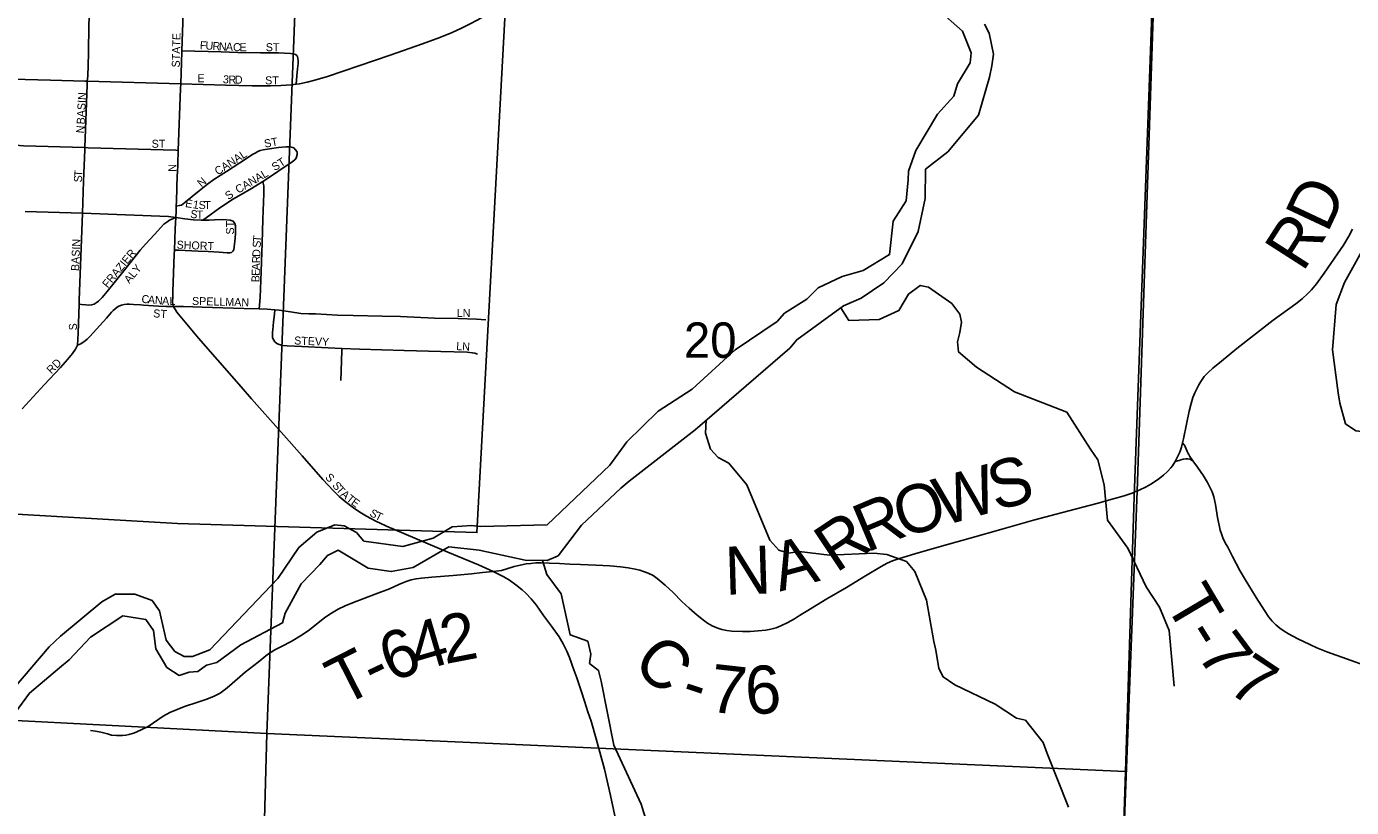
# Model space of a CAD drawing. Extents: x 0 to 34, y 0 to 22.
# Drawn here: x 4.796 to 6.364, y 17.372 to 18.295 of the extents above; entities that cross this region are included whole.
import ezdxf

# ---------------------------------------------------------------- set-up
doc = ezdxf.new("R2010")
doc.units = 0
for name, color, linetype in [('GM_X_City_Street', 7, 'Continuous'), ('GM_X_City_Street_Text', 7, 'Continuous'), ('GM_X_Corporation', 7, 'Continuous'), ('GM_X_County_Road', 7, 'Continuous'), ('GM_X_County_Road_Text', 7, 'Continuous'), ('GM_X_Minor_River', 7, 'Continuous'), ('GM_X_Section', 7, 'Continuous'), ('GM_X_Section_Text', 7, 'Continuous'), ('GM_X_Township', 7, 'Continuous'), ('GM_X_Township_Road', 7, 'Continuous'), ('GM_X_Township_Road_Text', 7, 'Continuous')]:
    doc.layers.add(name, color=color, linetype=linetype)

msp = doc.modelspace()

# ---------------------------------------------------------------- linework, layer by layer
at = {"layer": 'GM_X_City_Street'}
for points in [[(4.8682, 18.2305), (4.8687, 18.2363), (4.8694, 18.2629), (4.8698, 18.2978), (4.8705, 18.3045), (4.8711, 18.3097)], [(4.98, 18.2664), (4.981, 18.2999), (4.9811, 18.3058)], [(5.1151, 18.2271), (5.1191, 18.2276), (5.1284, 18.2294), (5.1375, 18.2316), (5.1525, 18.2361), (5.2263, 18.2613), (5.2647, 18.2746), (5.2852, 18.2822), (5.2997, 18.288), (5.311, 18.2933), (5.3194, 18.2975), (5.3303, 18.3032), (5.3347, 18.3059)], [(4.9787, 18.2274), (4.9799, 18.2657), (4.98, 18.2664)], [(4.98, 18.2664), (5.0264, 18.2653), (5.0464, 18.2644), (5.0731, 18.2641), (5.0945, 18.2639), (5.1084, 18.2634), (5.1117, 18.2629), (5.1144, 18.2622), (5.1159, 18.261)], [(5.1151, 18.2271), (5.116, 18.2367), (5.1169, 18.2452), (5.1173, 18.2484), (5.1175, 18.2516), (5.1175, 18.2547), (5.1173, 18.2578), (5.117, 18.2593), (5.1159, 18.261)], [(4.7065, 18.2354), (4.7098, 18.2351), (4.7498, 18.2337), (4.8247, 18.2318), (4.8651, 18.2306), (4.8682, 18.2305)], [(4.8652, 18.152), (4.8679, 18.2262), (4.8682, 18.2305)], [(4.8682, 18.2305), (4.9787, 18.2274)], [(4.9757, 18.1487), (4.9785, 18.2219), (4.9787, 18.2274)], [(4.9787, 18.2274), (5.0318, 18.2259), (5.063, 18.225), (5.0848, 18.2249), (5.0973, 18.2253), (5.1098, 18.2263), (5.1151, 18.2271)], [(4.7769, 18.1564), (4.7804, 18.1553), (4.7834, 18.1548), (4.7926, 18.1542), (4.8652, 18.152)], [(4.8624, 18.0744), (4.8638, 18.1124), (4.8651, 18.1493), (4.8652, 18.152)], [(4.8652, 18.152), (4.8692, 18.1519), (4.9727, 18.1488), (4.9757, 18.1487)], [(4.9734, 18.0828), (4.977, 18.0834), (4.9794, 18.0841), (4.9811, 18.0852), (4.984, 18.0874), (5.0003, 18.1007), (5.0103, 18.1086), (5.0177, 18.1141), (5.033, 18.1237), (5.0563, 18.1391), (5.0641, 18.1441), (5.0668, 18.1456), (5.07, 18.1474), (5.0728, 18.1484), (5.0761, 18.1493), (5.0837, 18.1505), (5.0943, 18.1521), (5.1033, 18.1529), (5.1064, 18.1531), (5.1094, 18.1527), (5.1112, 18.1522), (5.1123, 18.1516), (5.1145, 18.1495)], [(4.9747, 18.1218), (4.9751, 18.133), (4.9757, 18.1487)], [(5.0758, 18.1119), (5.0779, 18.1131), (5.1104, 18.1352), (5.1135, 18.1377), (5.1154, 18.1397), (5.1165, 18.1439), (5.1165, 18.1454), (5.1163, 18.1465), (5.1161, 18.1473), (5.1145, 18.1495)], [(4.9734, 18.0828), (4.9735, 18.0887), (4.9746, 18.1199), (4.9747, 18.1218)], [(5.0049, 18.0663), (5.0089, 18.0691), (5.0251, 18.0807), (5.0412, 18.0914), (5.0502, 18.0965), (5.0623, 18.1038), (5.0758, 18.1119)], [(5.0715, 17.9613), (5.0718, 17.9655), (5.0725, 17.9748), (5.0737, 18.0056), (5.0752, 18.0394), (5.0759, 18.0669), (5.077, 18.0977), (5.077, 18.1036), (5.0768, 18.1067), (5.0762, 18.1098), (5.0758, 18.1119)], [(4.7946, 18.0763), (4.8624, 18.0744)], [(4.8584, 17.9667), (4.8586, 17.9714), (4.8624, 18.0744)], [(4.8624, 18.0744), (4.9642, 18.0704), (4.9728, 18.0692)], [(4.9728, 18.0692), (4.9732, 18.0768), (4.9734, 18.0828)], [(4.8584, 17.9667), (4.8612, 17.9665), (4.8666, 17.966), (4.8701, 17.9656), (4.8732, 17.9659), (4.8761, 17.9668), (4.8788, 17.9684), (4.8813, 17.9703), (4.8857, 17.9747), (4.8917, 17.982), (4.9115, 18.0062), (4.9308, 18.0308), (4.9369, 18.038), (4.9476, 18.0493), (4.9588, 18.0613), (4.9621, 18.0638), (4.9655, 18.066), (4.9728, 18.0692)], [(4.9713, 18.0308), (4.9723, 18.056), (4.9728, 18.0692)], [(4.9713, 18.0308), (4.9763, 18.0306), (4.9993, 18.0297), (5.0113, 18.0291), (5.0243, 18.0284), (5.0337, 18.0276), (5.0369, 18.0276), (5.0386, 18.028), (5.0404, 18.0294), (5.0414, 18.0312), (5.0419, 18.0345), (5.0426, 18.0409), (5.0434, 18.0501), (5.0436, 18.0564), (5.0433, 18.0596), (5.0426, 18.0623)], [(4.9728, 18.0692), (4.9834, 18.0678), (4.9937, 18.0667), (5.0029, 18.0663), (5.0049, 18.0663)], [(5.0049, 18.0663), (5.0122, 18.0663), (5.0185, 18.0666), (5.0279, 18.0668), (5.033, 18.0666), (5.0373, 18.0662), (5.0395, 18.0656), (5.0408, 18.0649), (5.0417, 18.0639), (5.0426, 18.0623)], [(4.9702, 17.9641), (4.9698, 17.9647), (4.9693, 17.9666), (4.969, 17.9696), (4.9692, 17.9757), (4.9694, 17.9819), (4.9711, 18.0256), (4.9713, 18.0308)], [(4.8566, 17.9182), (4.8604, 17.92), (4.8655, 17.9234), (4.868, 17.9256), (4.8711, 17.9285), (4.8908, 17.9503), (4.8967, 17.9573), (4.8987, 17.9593), (4.9011, 17.9615), (4.9036, 17.9634), (4.9053, 17.9645), (4.9087, 17.9657), (4.9117, 17.9663), (4.9151, 17.9668), (4.9179, 17.9668), (4.9227, 17.9666), (4.9309, 17.9662), (4.9346, 17.9658), (4.9522, 17.9646), (4.9614, 17.9641), (4.9702, 17.9641)], [(4.8566, 17.9182), (4.8573, 17.9327), (4.8584, 17.9667)], [(4.9702, 17.9641), (4.9759, 17.964), (4.9821, 17.964), (5.0039, 17.9635), (5.0532, 17.9619), (5.0715, 17.9613)], [(5.2287, 17.7015), (5.2265, 17.7025), (5.2096, 17.7104), (5.1986, 17.7161), (5.1906, 17.7209), (5.183, 17.726), (5.1731, 17.7335), (5.1661, 17.7395), (5.1595, 17.746), (5.1469, 17.7596), (5.1222, 17.7875), (5.0974, 17.8153), (5.0625, 17.8548), (5.0503, 17.869), (5.0223, 17.9012), (4.9999, 17.9268), (4.9759, 17.9551), (4.9741, 17.9575), (4.9724, 17.9601), (4.9709, 17.9626), (4.9702, 17.9641)], [(5.0715, 17.9613), (5.081, 17.961), (5.0901, 17.9603)], [(5.0901, 17.9603), (5.0896, 17.9552), (5.0886, 17.946), (5.0875, 17.9367), (5.0872, 17.9336), (5.0871, 17.9302), (5.0874, 17.9276), (5.088, 17.9256), (5.0889, 17.9241), (5.0902, 17.9222), (5.0922, 17.9205), (5.0953, 17.9191), (5.0994, 17.918), (5.1047, 17.9175), (5.1219, 17.9167), (5.1529, 17.9151), (5.1693, 17.9145)], [(5.0901, 17.9603), (5.095, 17.9598), (5.1085, 17.9577), (5.1207, 17.9557), (5.1302, 17.9553), (5.1381, 17.9555), (5.151, 17.9547), (5.1641, 17.9539), (5.1827, 17.9533), (5.2169, 17.9528), (5.2386, 17.9522), (5.2789, 17.9505), (5.3069, 17.9498), (5.3286, 17.9491), (5.3395, 17.9484)], [(4.791, 17.843), (4.8172, 17.8715), (4.8363, 17.892), (4.8447, 17.9013), (4.8506, 17.9084), (4.8544, 17.9137), (4.8566, 17.9182)], [(5.1682, 17.8764), (5.1693, 17.9117), (5.1693, 17.9145)], [(5.1693, 17.9145), (5.1901, 17.9138), (5.2429, 17.9121), (5.2864, 17.911), (5.3174, 17.9101), (5.3235, 17.9095), (5.3266, 17.9089), (5.3296, 17.9079)]]:
    msp.add_lwpolyline(points, dxfattribs=at)
at = {"layer": 'GM_X_Corporation'}
msp.add_lwpolyline([(5.3632, 18.3273), (5.329, 17.6967), (4.9748, 17.7073), (4.5871, 17.7299)], dxfattribs=at)
at = {"layer": 'GM_X_County_Road'}
for points in [[(6.1637, 17.8028), (6.1649, 17.8078), (6.1685, 17.825), (6.1718, 17.8405), (6.1741, 17.8495), (6.1761, 17.8565), (6.1784, 17.8621), (6.1806, 17.8669), (6.1831, 17.8716), (6.1853, 17.8756), (6.1893, 17.8812), (6.1941, 17.8862), (6.1998, 17.8911), (6.2097, 17.8994), (6.2279, 17.9145), (6.2708, 17.9479), (6.2979, 17.9673), (6.3052, 17.973), (6.312, 17.9793), (6.3163, 17.9838), (6.3221, 17.9909), (6.3312, 18.0035), (6.3471, 18.0264), (6.354, 18.0368), (6.3604, 18.0473), (6.3648, 18.0555)], [(6.1552, 17.7809), (6.158, 17.7863), (6.1605, 17.792), (6.1625, 17.7978), (6.1637, 17.8028)], [(6.1083, 17.7452), (6.11, 17.7459), (6.1126, 17.7469), (6.1209, 17.751), (6.1263, 17.754), (6.134, 17.7591), (6.1413, 17.7647), (6.1459, 17.7688), (6.15, 17.7734), (6.1519, 17.7758), (6.1552, 17.7809)], [(5.3483, 17.6507), (5.358, 17.6521), (5.3643, 17.6539), (5.373, 17.6565), (5.3822, 17.6586), (5.3873, 17.6597), (5.3927, 17.6602), (5.3989, 17.6609), (5.4051, 17.661), (5.4144, 17.6607), (5.4267, 17.6601), (5.4391, 17.6595), (5.4515, 17.659), (5.4607, 17.6586), (5.4699, 17.6582), (5.4862, 17.6574), (5.499, 17.6562), (5.5081, 17.655), (5.5162, 17.6536), (5.5217, 17.6522), (5.5262, 17.6508), (5.5316, 17.6489), (5.5375, 17.6458), (5.5423, 17.6425), (5.5472, 17.6386), (5.5516, 17.6347), (5.5613, 17.6258), (5.5715, 17.6153), (5.5801, 17.6074), (5.5898, 17.5992), (5.597, 17.5932), (5.6019, 17.5896), (5.6072, 17.5865), (5.6128, 17.584), (5.6187, 17.5822), (5.6247, 17.581), (5.6308, 17.5803), (5.6432, 17.5797), (5.6524, 17.5797), (5.6617, 17.5804), (5.6709, 17.5815), (5.6769, 17.5827), (5.6829, 17.5843), (5.6886, 17.5864), (5.6969, 17.5904), (5.7049, 17.5948), (5.7106, 17.5985), (5.7187, 17.6036), (5.7428, 17.6185), (5.7664, 17.6319), (5.7887, 17.6455), (5.8071, 17.6568), (5.8143, 17.6607), (5.8208, 17.6634), (5.8291, 17.6662), (5.847, 17.6715), (5.8648, 17.6766), (5.8857, 17.6825), (5.9125, 17.6903), (5.9514, 17.7013), (5.9873, 17.7113), (6.0143, 17.7186), (6.0293, 17.7226), (6.0623, 17.7313), (6.0833, 17.7369), (6.0949, 17.7403), (6.104, 17.7434), (6.1083, 17.7452)], [(5.3483, 17.6507), (5.3308, 17.6587), (5.2945, 17.6735), (5.2324, 17.6999), (5.2287, 17.7015)], [(5.4924, 17.3618), (5.487, 17.3859), (5.4798, 17.4168), (5.4703, 17.4529), (5.4643, 17.4738), (5.4604, 17.4846), (5.4565, 17.4972), (5.4528, 17.5085), (5.4474, 17.5251), (5.4438, 17.5346), (5.4386, 17.549), (5.4355, 17.5564), (5.4312, 17.5653), (5.4264, 17.5734), (5.4174, 17.5859), (5.408, 17.5988), (5.399, 17.6112), (5.3932, 17.6183), (5.3869, 17.625), (5.3824, 17.6292), (5.3752, 17.6351), (5.3677, 17.6403), (5.3609, 17.6445), (5.3483, 17.6507)]]:
    msp.add_lwpolyline(points, dxfattribs=at)
at = {"layer": 'GM_X_Minor_River'}
for points in [[(5.8766, 18.3132), (5.9036, 18.2898), (5.9136, 18.264), (5.9125, 18.2523), (5.8975, 18.2275), (5.8934, 18.2127), (5.8741, 18.1914), (5.8482, 18.1484), (5.8396, 18.1241), (5.8392, 18.1139), (5.8367, 18.0892), (5.8216, 18.0652), (5.8173, 18.0254), (5.7859, 18.0066), (5.7613, 17.9997), (5.7329, 17.9863), (5.7194, 17.9726), (5.6929, 17.9562), (5.6842, 17.9463), (5.6347, 17.913), (5.5838, 17.8662), (5.5433, 17.8402), (5.5064, 17.804), (5.4864, 17.7766), (5.412, 17.7061), (5.3332, 17.7038), (5.3226, 17.7053), (5.2999, 17.7037), (5.2772, 17.6903), (5.2416, 17.6803), (5.1953, 17.6866), (5.1866, 17.6968), (5.1721, 17.7047), (5.1611, 17.7058), (5.1396, 17.6973), (5.1184, 17.679), (5.0936, 17.6425), (5.0132, 17.5579), (4.9928, 17.5502), (4.9829, 17.5502), (4.9719, 17.5562), (4.9616, 17.5695), (4.9535, 17.6043), (4.9447, 17.6164), (4.9242, 17.6239), (4.9011, 17.6238), (4.8852, 17.615), (4.8365, 17.5742), (4.8229, 17.5616), (4.72, 17.4413)], [(4.7824, 17.4833), (4.7997, 17.5069), (4.8352, 17.5367), (4.8469, 17.5462), (4.8718, 17.5732), (4.9103, 17.5981), (4.9373, 17.594), (4.9464, 17.5808), (4.9492, 17.5592), (4.9622, 17.5372), (4.977, 17.5278), (4.9887, 17.5316), (4.9989, 17.5324), (5.0091, 17.5401), (5.0213, 17.5432), (5.0496, 17.5641), (5.0991, 17.5902), (5.1021, 17.6016), (5.1213, 17.6362), (5.1431, 17.659), (5.1522, 17.6697), (5.1651, 17.6758), (5.2004, 17.6547), (5.2277, 17.6507), (5.2535, 17.6553), (5.2958, 17.6798), (5.3318, 17.6758), (5.3861, 17.6642), (5.4122, 17.6636), (5.4251, 17.6693), (5.4526, 17.7055), (5.4994, 17.7493), (5.5092, 17.7577), (5.5874, 17.8184), (5.6992, 17.9148), (5.7074, 17.9247), (5.7626, 17.9648), (5.7838, 17.974), (5.8106, 17.992), (5.8321, 18.0144), (5.8509, 18.0528), (5.8594, 18.0919), (5.8596, 18.1265), (5.8861, 18.1471), (5.9223, 18.1905), (5.9353, 18.2353), (5.9383, 18.2486), (5.9401, 18.2626), (5.9351, 18.2873), (5.9294, 18.2979)], [(6.3781, 18.296), (6.3851, 18.2627), (6.3993, 18.2255), (6.4005, 18.2085), (6.3962, 18.1698), (6.3968, 18.1038), (6.3936, 18.0757), (6.3835, 18.043), (6.3553, 17.9924), (6.3456, 17.9666), (6.3413, 17.9127), (6.3479, 17.8619), (6.3499, 17.8497), (6.3564, 17.8255), (6.3686, 17.8172), (6.4031, 17.8132), (6.4258, 17.8175), (6.4533, 17.7846), (6.4659, 17.7531), (6.4774, 17.7414), (6.5221, 17.7306), (6.5347, 17.7212), (6.5519, 17.6962), (6.563, 17.6697)], [(5.7595, 17.9626), (5.7691, 17.9474), (5.8051, 17.9487), (5.8282, 17.9594), (5.8395, 17.9788), (5.8535, 17.9891), (5.8633, 17.9869), (5.8907, 17.9676), (5.9002, 17.9552), (5.9022, 17.9457), (5.9003, 17.9332), (5.8974, 17.9225), (5.8989, 17.9104), (5.9199, 17.8923), (5.9651, 17.8633), (6.027, 17.8392), (6.0549, 17.7954), (6.0636, 17.7829), (6.071, 17.7533), (6.075, 17.7116), (6.099, 17.6783), (6.1208, 17.6325), (6.1365, 17.6087), (6.148, 17.581), (6.1539, 17.5151)], [(5.6003, 17.8295), (5.5996, 17.8143), (5.6053, 17.7953), (5.6145, 17.7855), (5.627, 17.7787), (5.6483, 17.7534), (5.6756, 17.6879), (5.6862, 17.6758), (5.6976, 17.6724), (5.7101, 17.6744), (5.7461, 17.67), (5.7984, 17.6725), (5.814, 17.671), (5.8372, 17.6624), (5.8471, 17.6507), (5.8609, 17.617), (5.8694, 17.5681), (5.8721, 17.5578), (5.8753, 17.5362), (5.8806, 17.526), (5.8943, 17.5166), (5.9422, 17.494), (5.9673, 17.4774), (5.9779, 17.4748), (5.9988, 17.4484), (6.0038, 17.4355), (6.0288, 17.3719)], [(5.4067, 17.6637), (5.4116, 17.6473), (5.4287, 17.6242), (5.4392, 17.5757), (5.4601, 17.5682), (5.4639, 17.553), (5.4621, 17.542), (5.4727, 17.5337), (5.4762, 17.5212), (5.491, 17.4454), (5.5235, 17.3754), (5.535, 17.3375)]]:
    msp.add_lwpolyline(points, dxfattribs=at)
at = {"layer": 'GM_X_Section'}
for points in [[(4.1166, 18.5074), (5.1195, 18.4619), (5.0805, 17.4591), (4.0746, 17.5111)], [(5.1195, 18.4619), (6.1311, 18.4108), (6.125, 18.2446), (6.1067, 17.7389), (6.0962, 17.4141), (5.0805, 17.4591)], [(4.0746, 17.5111), (5.0805, 17.4591), (5.0528, 16.4469), (4.8222, 16.4519), (4.5034, 16.4581), (4.0244, 16.4784)], [(6.0962, 17.4141), (6.0907, 17.2474), (6.0735, 16.7271), (6.0629, 16.4049), (5.594, 16.4244), (5.073, 16.4461), (5.0528, 16.4469), (5.0805, 17.4591)]]:
    msp.add_lwpolyline(points, close=True, dxfattribs=at)
at = {"layer": 'GM_X_Township'}
for points in [[(2.6013, 16.5379), (2.8688, 16.5234), (3.5006, 16.5009), (4.2928, 16.4705), (5.2983, 16.434), (6.0664, 16.4042), (6.0778, 16.7443), (6.0911, 17.2548), (6.11, 17.7459), (6.1473, 18.845), (6.1717, 19.6397), (6.1731, 19.6616), (6.1731, 19.6818), (6.1733, 19.6859), (6.2234, 21.2003)], [(6.2234, 21.2003), (6.1733, 19.6859), (6.1731, 19.6818), (6.1731, 19.6616), (6.1717, 19.6397), (6.1473, 18.845), (6.11, 17.7459), (6.0911, 17.2548), (6.0778, 16.7443), (6.0664, 16.4042), (6.0598, 16.2379), (6.2085, 16.2337), (6.3056, 16.228), (6.5048, 16.2253), (7.5772, 16.1862), (7.7357, 16.1804), (8.4842, 16.1527), (8.5405, 16.1503), (9.1818, 16.131), (9.4013, 16.1226)]]:
    msp.add_lwpolyline(points, dxfattribs=at)
at = {"layer": 'GM_X_Township_Road'}
for points in [[(6.1637, 17.8028), (6.1656, 17.8005), (6.1667, 17.7986), (6.1676, 17.7964), (6.1692, 17.7926), (6.17, 17.7909), (6.1711, 17.7891), (6.1724, 17.7869), (6.1761, 17.7816)], [(6.1552, 17.7809), (6.1578, 17.7814), (6.1598, 17.7819), (6.1619, 17.7826), (6.1646, 17.7835), (6.1677, 17.7838), (6.1702, 17.7839), (6.1726, 17.7834), (6.1761, 17.7816)], [(6.1761, 17.7816), (6.1815, 17.7741), (6.1884, 17.7638), (6.1933, 17.7559), (6.1962, 17.7504), (6.1987, 17.7448), (6.2007, 17.7389), (6.2028, 17.7299), (6.2052, 17.7146), (6.2071, 17.7054), (6.2084, 17.6997), (6.2098, 17.6954), (6.2114, 17.6906), (6.2144, 17.6848), (6.2173, 17.6795), (6.2228, 17.6683), (6.2316, 17.652), (6.2378, 17.6413), (6.2507, 17.6201), (6.2606, 17.6045), (6.266, 17.5969), (6.2699, 17.5921), (6.2742, 17.5876), (6.2788, 17.5836), (6.2839, 17.58), (6.2893, 17.5769), (6.3003, 17.5712), (6.3142, 17.5642), (6.3227, 17.5604), (6.3343, 17.5558), (6.3577, 17.5475), (6.3841, 17.5381)], [(5.2416, 17.6372), (5.2453, 17.6388), (5.2511, 17.6407), (5.2571, 17.6421), (5.2635, 17.6428), (5.2758, 17.6439), (5.3008, 17.6458), (5.3227, 17.6478), (5.3357, 17.6494), (5.3483, 17.6507)], [(4.8721, 17.4625), (4.8777, 17.4618), (4.8842, 17.4606), (4.8919, 17.4587), (4.8968, 17.4573), (4.9027, 17.4566), (4.9064, 17.4566), (4.9097, 17.4568), (4.9139, 17.4571), (4.9174, 17.4578), (4.9234, 17.4597), (4.932, 17.4634), (4.94, 17.4676), (4.9463, 17.4718), (4.9578, 17.4795), (4.9659, 17.4839), (4.9744, 17.4877), (4.983, 17.491), (4.9978, 17.4958), (5.0095, 17.4998), (5.0182, 17.5034), (5.0238, 17.5061), (5.0264, 17.5077), (5.029, 17.5095), (5.0315, 17.5114), (5.0362, 17.5155), (5.0551, 17.5315), (5.0701, 17.5436), (5.0815, 17.5527), (5.09, 17.5581), (5.0979, 17.5621), (5.1093, 17.5679), (5.1222, 17.576), (5.131, 17.5819), (5.1493, 17.5963), (5.1571, 17.6014), (5.1651, 17.6061), (5.1733, 17.6102), (5.1819, 17.6138), (5.2085, 17.6239), (5.2257, 17.6304), (5.2368, 17.6352), (5.2416, 17.6372)]]:
    msp.add_lwpolyline(points, dxfattribs=at)

# ---------------------------------------------------------------- texts
at = {"layer": 'GM_X_City_Street_Text'}
for s, rotation, p in [('STATE', 88.6634, (4.9775, 18.2467)), ('F', 356.8293, (5.0011, 18.2685)), ('U', 356.8515, (5.0078, 18.2681)), ('R', 356.8417, (5.0161, 18.2676)), ('N', 356.8287, (5.0236, 18.2672)), ('A', 356.8515, (5.0319, 18.2668)), ('C', 357.8199, (5.0404, 18.2663)), ('E', 359.6942, (5.0482, 18.266)), ('ST', 0, (5.0793, 18.266)), ('E', 0, (4.9985, 18.2293)), ('3', 353.6805, (5.0282, 18.2284)), ('R', 359.5265, (5.0351, 18.2277)), ('D', 0.0115, (5.0427, 18.2276)), ('ST', 0, (5.0785, 18.2268)), ('BASIN', 87.2752, (4.865, 18.1793)), ('N', 84.2937, (4.8642, 18.1685)), ('ST', 0, (4.9443, 18.1518)), ('ST', 10.6288, (5.0783, 18.1518)), ('CANAL', 33.1455, (5.0226, 18.119)), ('ST', 32.7431, (5.09, 18.124)), ('T', 85.9806, (4.8621, 18.1173)), ('N', 90, (4.9734, 18.1234)), ('CANAL', 30.5775, (5.0468, 18.0974)), ('S', 86.9384, (4.8617, 18.1107)), ('N', 40.6039, (5.0032, 18.1047)), ('E', 351.1936, (4.9835, 18.0818)), ('1', 351.218, (4.9925, 18.0804)), ('S', 359.3679, (4.9998, 18.0794)), ('T', 359.9956, (5.0065, 18.0793)), ('S', 33.6985, (5.035, 18.0898)), ('S', 352.3566, (4.9896, 18.0691)), ('T', 359.4812, (4.9975, 18.0681)), ('ST', 90, (5.0417, 18.0492)), ('BASIN', 87.7987, (4.8584, 18.0059)), ('SHORT', 357.4519, (4.9736, 18.0326)), ('S', 87.2126, (5.0732, 18.0334)), ('T', 85.3498, (5.0735, 18.04)), ('FRAZIER', 50.5721, (4.8922, 17.9853)), ('D', 87.9436, (5.0728, 18.0226)), ('ALY', 50.4398, (4.9179, 17.9906)), ('A', 87.9549, (5.0722, 18.0068)), ('R', 87.9355, (5.0725, 18.0151)), ('B', 87.9355, (5.0717, 17.9926)), ('E', 87.9332, (5.072, 18.0001)), ('C', 355.1617, (4.932, 17.9685)), ('A', 355.142, (4.9395, 17.9678)), ('N', 355.142, (4.9478, 17.9671)), ('A', 357.2457, (4.9564, 17.9664)), ('L', 359.9073, (4.9652, 17.966)), ('SPELLMAN', 358.4315, (4.9919, 17.966)), ('ST', 356.4254, (4.9459, 17.9514)), ('LN', 0, (5.3052, 17.9518)), ('S', 90, (4.8559, 17.9359)), ('STEVY', 357.4567, (5.1127, 17.9193)), ('LN', 356.9884, (5.3044, 17.9126)), ('RD', 45, (4.8256, 17.8838)), ('S', 314.9818, (5.1489, 17.7613)), ('S', 310.8235, (5.1574, 17.752)), ('T', 311.8068, (5.1618, 17.7468)), ('A', 319.0533, (5.1672, 17.7409)), ('T', 321.5311, (5.1738, 17.7352)), ('E', 323.6403, (5.1794, 17.7308)), ('S', 328.6754, (5.2012, 17.7173)), ('T', 334.458, (5.2078, 17.7134))]:
    msp.add_text(s, height=0.00947, rotation=rotation, dxfattribs=at).set_placement(p)
at = {"layer": 'GM_X_County_Road_Text'}
for s, rotation, p in [('D', 64.8659, (6.3351, 18.0499)), ('R', 57.3773, (6.3061, 18.0037)), ('W', 15.7516, (5.8794, 17.7041)), ('S', 15.7528, (5.9428, 17.722)), ('O', 16.15, (5.8315, 17.6902)), ('R', 22.7763, (5.7901, 17.6727)), ('R', 33.7316, (5.7538, 17.6482)), ('N', 1.7232, (5.623, 17.6232)), ('A', 15.1275, (5.6873, 17.6268)), ('C', 318.5181, (5.511, 17.5388)), ('7', 353.5556, (5.6023, 17.4853)), ('6', 3.9675, (5.6483, 17.4812)), ('-', 341.6672, (5.5676, 17.4954))]:
    msp.add_text(s, height=0.0568, rotation=rotation, dxfattribs=at).set_placement(p)
at = {"layer": 'GM_X_Section_Text'}
msp.add_text('20', height=0.04186, rotation=0, dxfattribs=at).set_placement((5.5739, 17.9034))
at = {"layer": 'GM_X_Township_Road_Text'}
for s, rotation, p in [('T', 300.6778, (6.1417, 17.6137)), ('2', 10.9058, (5.2913, 17.5411)), ('4', 16.2721, (5.259, 17.5316)), ('-', 302.0183, (6.1641, 17.576)), ('6', 21.4033, (5.2277, 17.5193)), ('7', 306.7331, (6.1793, 17.552)), ('T', 26.9503, (5.1701, 17.4906)), ('-', 25.4409, (5.2076, 17.5097)), ('7', 326.1212, (6.2151, 17.5098))]:
    msp.add_text(s, height=0.0568, rotation=rotation, dxfattribs=at).set_placement(p)

doc.saveas('drawing.dxf')
